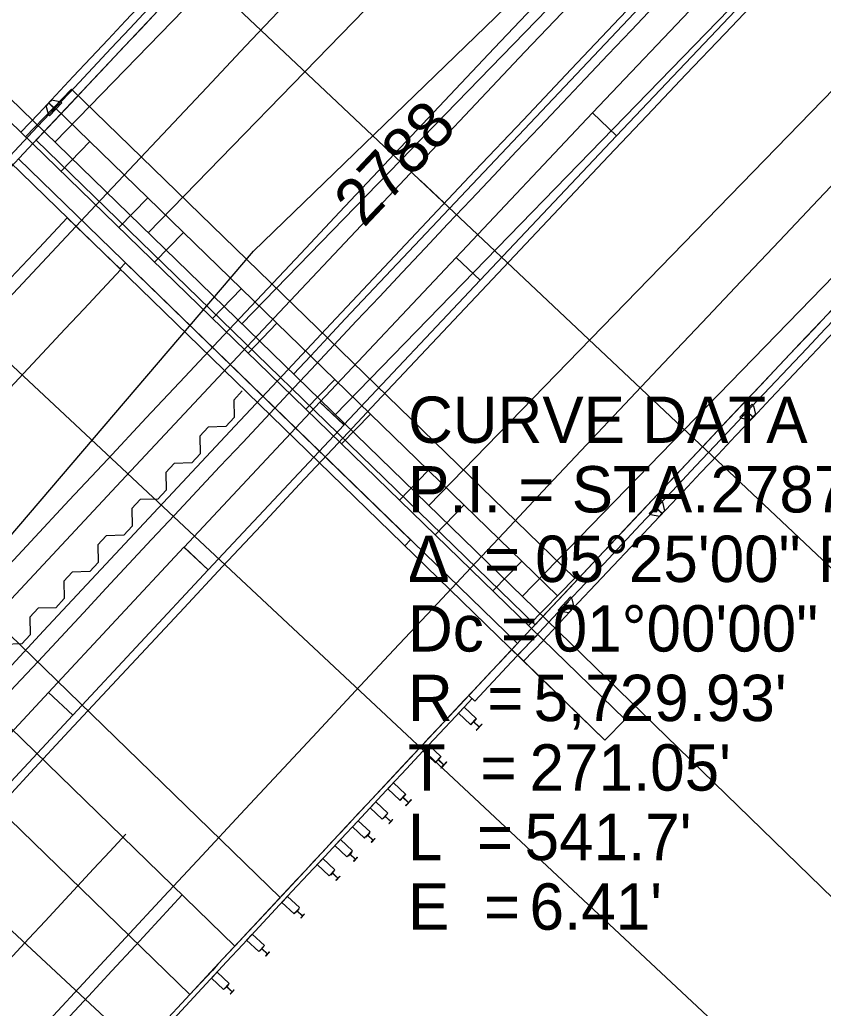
# Model space of a CAD drawing. Extents: x 2376379 to 2383101, y 559608 to 561720.
# Drawn here: x 2376981.5 to 2377030.1, y 561165 to 561224.7 of the extents above; entities that cross this region are included whole.
import ezdxf

# ---------------------------------------------------------------- set-up
doc = ezdxf.new("R2010")
doc.units = 0
for name, color, linetype in [('BR_X_SV_Bottom_of_Beam', 7, 'Continuous'), ('BR_X_SV_Deck_Top', 7, 'Continuous'), ('DR_X_Headwall', 7, 'Continuous'), ('DR_X_Storm_Sewer', 7, 'Continuous'), ('DT_X_Terrain_Ground_Line', 7, 'Continuous'), ('HY_X_Water_Edge', 7, 'Continuous'), ('PM_X_CL_Dashed', 7, 'Continuous'), ('PM_X_CL_Pass_Proh_Lt', 7, 'Continuous'), ('PM_X_Edge_Line', 7, 'Continuous'), ('PM_X_Surveyed_Line', 7, 'Continuous'), ('PV_X_COP', 7, 'Continuous'), ('PV_X_EOP', 7, 'Continuous'), ('PV_X_Shoulder', 7, 'Continuous'), ('RD_X_Cells', 7, 'Continuous'), ('RD_X_GR_Lt', 7, 'Continuous'), ('SC_Scratch1', 7, 'Continuous'), ('SV_X_Break_Lines', 7, 'Continuous'), ('SV_X_Control_Cells_Found', 7, 'Continuous'), ('SV_X_Text', 7, 'Continuous'), ('UT_X_Gas_Cells', 7, 'Continuous')]:
    doc.layers.add(name, color=color, linetype=linetype)

msp = doc.modelspace()

# ---------------------------------------------------------------- linework, layer by layer
at = {"layer": 'BR_X_SV_Bottom_of_Beam'}
for p, q in [((2377024.396, 561227.73), (2377016.136, 561219.025)), ((2377025.847, 561226.353), (2377017.587, 561217.648)), ((2377016.135, 561219.023), (2377007.893, 561210.301)), ((2377016.135, 561219.023), (2377007.893, 561210.301)), ((2377016.135, 561219.023), (2377017.588, 561217.65)), ((2377016.135, 561219.023), (2377017.588, 561217.65)), ((2377016.136, 561219.025), (2377017.587, 561217.648)), ((2377017.588, 561217.65), (2377009.347, 561208.927)), ((2377017.588, 561217.65), (2377009.347, 561208.927)), ((2377007.892, 561210.299), (2376999.669, 561201.56)), ((2377007.892, 561210.299), (2377009.348, 561208.929)), ((2377007.893, 561210.301), (2377009.347, 561208.927)), ((2377007.893, 561210.301), (2377009.347, 561208.927)), ((2377009.348, 561208.929), (2377001.125, 561200.189)), ((2376999.667, 561201.558), (2376991.462, 561192.802)), ((2376999.667, 561201.558), (2377001.127, 561200.191)), ((2376999.669, 561201.56), (2377001.125, 561200.189)), ((2377001.127, 561200.191), (2376992.922, 561191.434)), ((2376991.461, 561192.8), (2376983.275, 561184.026)), ((2376991.461, 561192.8), (2376992.923, 561191.436)), ((2376991.462, 561192.802), (2376992.922, 561191.434)), ((2376992.923, 561191.436), (2376984.737, 561182.662)), ((2376983.273, 561184.025), (2376975.105, 561175.234)), ((2376983.273, 561184.025), (2376984.738, 561182.663)), ((2376983.275, 561184.026), (2376984.737, 561182.662)), ((2376984.738, 561182.663), (2376976.57, 561173.872))]:
    msp.add_line(p, q, dxfattribs=at)
for radius in [5724.68, 5713.68]:
    msp.add_arc((2381174.86, 557281.309), radius, 134.056462, 138.414594, dxfattribs=at)
at = {"layer": 'BR_X_SV_Deck_Top'}
msp.add_line((2376984.409, 561212.699), (2376987.637, 561209.563), dxfattribs=at)
for radius, start, end in [(5745.93, 136.8269349, 138.4145938), (5741.43, 136.8277185, 138.9145631)]:
    msp.add_arc((2381174.86, 557281.309), radius, start, end, dxfattribs=at)
at = {"layer": 'DR_X_Headwall'}
msp.add_arc((2381174.86, 557281.309), 5712.93, 137.078423, 138.414594, dxfattribs=at)
at = {"layer": 'DR_X_Storm_Sewer'}
for p, q in [((2376981.472, 561216.25), (2377011.6, 561186.979)), ((2376964.404, 561197.983), (2376994.536, 561168.709))]:
    msp.add_line(p, q, dxfattribs=at)
msp.add_arc((2381174.917, 557281.256), 5708.58, 136.828468, 137.079388, dxfattribs=at)
at = {"layer": 'DT_X_Terrain_Ground_Line'}
for p, q in [((2376967.13, 561200.911), (2376997.261, 561171.638)), ((2376961.68, 561195.052), (2376991.812, 561165.778))]:
    msp.add_line(p, q, dxfattribs=at)
msp.add_arc((2381174.86, 557281.309), 5708.502, 137.039237, 137.119552, dxfattribs=at)
at = {"layer": 'HY_X_Water_Edge'}
msp.add_line((2376918.197, 561280.86), (2377079.942, 561123.72), dxfattribs=at)
at = {"layer": 'PM_X_CL_Dashed'}
for p, q in [((2377025.645, 561201.168), (2377025.302, 561200.805)), ((2377025.66, 561201.153), (2377025.496, 561200.979)), ((2377025.645, 561201.168), (2377025.845, 561201.38)), ((2377025.645, 561201.168), (2377025.66, 561201.153)), ((2377025.845, 561201.38), (2377025.785, 561201.438)), ((2377025.853, 561201.328), (2377025.823, 561201.357)), ((2377025.853, 561201.328), (2377025.976, 561200.823)), ((2377025.101, 561200.593), (2377025.041, 561200.65)), ((2377025.101, 561200.593), (2377025.302, 561200.805)), ((2377025.154, 561200.587), (2377025.123, 561200.616)), ((2377025.154, 561200.587), (2377025.665, 561200.494)), ((2377025.302, 561200.805), (2377025.318, 561200.79)), ((2377025.482, 561200.965), (2377025.318, 561200.79)), ((2377025.482, 561200.965), (2377025.814, 561200.652)), ((2377025.496, 561200.979), (2377025.827, 561200.666)), ((2377025.814, 561200.652), (2377025.649, 561200.477)), ((2377025.649, 561200.477), (2377025.665, 561200.462)), ((2377026.007, 561200.825), (2377025.665, 561200.462)), ((2377025.992, 561200.84), (2377025.827, 561200.666)), ((2377025.992, 561200.84), (2377026.007, 561200.825)), ((2377020.155, 561195.349), (2377019.813, 561194.986)), ((2377019.993, 561195.146), (2377019.829, 561194.971)), ((2377019.993, 561195.146), (2377020.325, 561194.833)), ((2377020.171, 561195.334), (2377020.007, 561195.16)), ((2377020.007, 561195.16), (2377020.338, 561194.847)), ((2377020.155, 561195.349), (2377020.356, 561195.562)), ((2377020.155, 561195.349), (2377020.171, 561195.334)), ((2377020.356, 561195.562), (2377020.295, 561195.619)), ((2377020.364, 561195.51), (2377020.334, 561195.539)), ((2377020.364, 561195.51), (2377020.487, 561195.005)), ((2377019.613, 561194.773), (2377019.552, 561194.831)), ((2377019.613, 561194.773), (2377019.813, 561194.986)), ((2377019.665, 561194.768), (2377019.635, 561194.797)), ((2377019.665, 561194.768), (2377020.177, 561194.676)), ((2377019.813, 561194.986), (2377019.829, 561194.971)), ((2377020.325, 561194.833), (2377020.161, 561194.659)), ((2377020.161, 561194.659), (2377020.176, 561194.644)), ((2377020.519, 561195.007), (2377020.176, 561194.644)), ((2377020.503, 561195.022), (2377020.338, 561194.847)), ((2377020.503, 561195.022), (2377020.519, 561195.007)), ((2377014.674, 561189.523), (2377014.874, 561189.736)), ((2377014.874, 561189.736), (2377014.813, 561189.793)), ((2377014.883, 561189.684), (2377014.852, 561189.713)), ((2377014.132, 561188.946), (2377014.332, 561189.159)), ((2377014.674, 561189.523), (2377014.332, 561189.159)), ((2377014.332, 561189.159), (2377014.348, 561189.144)), ((2377014.513, 561189.319), (2377014.348, 561189.144)), ((2377014.513, 561189.319), (2377014.845, 561189.007)), ((2377014.69, 561189.508), (2377014.526, 561189.333)), ((2377014.526, 561189.333), (2377014.858, 561189.021)), ((2377014.674, 561189.523), (2377014.69, 561189.508)), ((2377015.038, 561189.181), (2377014.696, 561188.817)), ((2377015.022, 561189.196), (2377014.858, 561189.021)), ((2377014.883, 561189.684), (2377015.006, 561189.179)), ((2377015.022, 561189.196), (2377015.038, 561189.181)), ((2377014.132, 561188.946), (2377014.072, 561189.003)), ((2377014.185, 561188.941), (2377014.154, 561188.97)), ((2377014.185, 561188.941), (2377014.697, 561188.849)), ((2377014.845, 561189.007), (2377014.68, 561188.832)), ((2377014.68, 561188.832), (2377014.696, 561188.817)), ((2377009.03, 561183.507), (2377008.666, 561183.849)), ((2377008.038, 561182.767), (2377008.38, 561183.132)), ((2377009.11, 561182.448), (2377008.38, 561183.132)), ((2377008.768, 561182.083), (2377008.038, 561182.767)), ((2377009.109, 561182.448), (2377008.768, 561182.084)), ((2377008.768, 561182.084), (2377008.784, 561182.069)), ((2377008.948, 561182.244), (2377008.784, 561182.069)), ((2377008.948, 561182.244), (2377009.281, 561181.932)), ((2377009.125, 561182.433), (2377008.961, 561182.258)), ((2377008.961, 561182.258), (2377009.294, 561181.946)), ((2377009.109, 561182.448), (2377009.125, 561182.433)), ((2377009.474, 561182.107), (2377009.132, 561181.742)), ((2377009.458, 561182.122), (2377009.294, 561181.946)), ((2377009.458, 561182.122), (2377009.474, 561182.107)), ((2377009.281, 561181.932), (2377009.117, 561181.757)), ((2377009.117, 561181.757), (2377009.132, 561181.742)), ((2377005.903, 561180.485), (2377006.244, 561180.85)), ((2377006.975, 561180.167), (2377006.244, 561180.85)), ((2377006.633, 561179.802), (2377005.903, 561180.485)), ((2377006.974, 561180.167), (2377006.633, 561179.802)), ((2377006.99, 561180.152), (2377006.826, 561179.977)), ((2377006.974, 561180.167), (2377006.99, 561180.152)), ((2377006.633, 561179.802), (2377006.649, 561179.788)), ((2377006.813, 561179.963), (2377006.649, 561179.788)), ((2377006.813, 561179.963), (2377007.146, 561179.652)), ((2377006.826, 561179.977), (2377007.159, 561179.666)), ((2377007.146, 561179.652), (2377006.982, 561179.476)), ((2377007.339, 561179.826), (2377006.998, 561179.461)), ((2377007.323, 561179.841), (2377007.159, 561179.666)), ((2377007.323, 561179.841), (2377007.339, 561179.826)), ((2377006.982, 561179.476), (2377006.998, 561179.461)), ((2377003.769, 561178.202), (2377004.11, 561178.568)), ((2377004.841, 561177.885), (2377004.11, 561178.568)), ((2377004.5, 561177.52), (2377003.769, 561178.202)), ((2377004.841, 561177.885), (2377004.5, 561177.52)), ((2377004.856, 561177.87), (2377004.693, 561177.695)), ((2377004.841, 561177.885), (2377004.856, 561177.87)), ((2377002.702, 561177.061), (2377003.044, 561177.426)), ((2377003.775, 561176.744), (2377003.044, 561177.426)), ((2377004.5, 561177.52), (2377004.516, 561177.505)), ((2377004.68, 561177.681), (2377004.516, 561177.505)), ((2377004.68, 561177.681), (2377005.013, 561177.369)), ((2377004.693, 561177.695), (2377005.026, 561177.383)), ((2377005.013, 561177.369), (2377004.849, 561177.194)), ((2377004.849, 561177.194), (2377004.865, 561177.179)), ((2377005.205, 561177.544), (2377004.865, 561177.179)), ((2377005.19, 561177.559), (2377005.026, 561177.383)), ((2377005.19, 561177.559), (2377005.205, 561177.544)), ((2377003.433, 561176.378), (2377002.702, 561177.061)), ((2377003.716, 561176.681), (2377003.492, 561176.441)), ((2377003.729, 561176.669), (2377003.622, 561176.554)), ((2377003.716, 561176.681), (2377003.775, 561176.744)), ((2377003.729, 561176.669), (2377003.716, 561176.681)), ((2377001.636, 561175.919), (2377001.977, 561176.284)), ((2377002.708, 561175.602), (2377001.977, 561176.284)), ((2377003.433, 561176.378), (2377003.492, 561176.441)), ((2377003.492, 561176.441), (2377003.505, 561176.429)), ((2377003.612, 561176.543), (2377003.505, 561176.429)), ((2377003.945, 561176.232), (2377003.612, 561176.543)), ((2377003.955, 561176.243), (2377003.622, 561176.554)), ((2377003.945, 561176.232), (2377003.838, 561176.118)), ((2377003.838, 561176.118), (2377003.851, 561176.105)), ((2377004.075, 561176.345), (2377003.851, 561176.105)), ((2377004.062, 561176.357), (2377003.955, 561176.243)), ((2377004.062, 561176.357), (2377004.075, 561176.345)), ((2377002.367, 561175.236), (2377001.636, 561175.919)), ((2377002.65, 561175.539), (2377002.426, 561175.299)), ((2377002.546, 561175.402), (2377002.439, 561175.287)), ((2377002.879, 561175.091), (2377002.546, 561175.402)), ((2377002.663, 561175.527), (2377002.556, 561175.412)), ((2377002.889, 561175.101), (2377002.556, 561175.412)), ((2377002.65, 561175.539), (2377002.708, 561175.602)), ((2377002.663, 561175.527), (2377002.65, 561175.539)), ((2377000.57, 561174.776), (2377000.911, 561175.142)), ((2377001.302, 561174.094), (2377000.57, 561174.776)), ((2377001.643, 561174.46), (2377000.911, 561175.142)), ((2377002.367, 561175.236), (2377002.426, 561175.299)), ((2377002.426, 561175.299), (2377002.439, 561175.287)), ((2377002.879, 561175.091), (2377002.772, 561174.976)), ((2377002.772, 561174.976), (2377002.785, 561174.963)), ((2377003.009, 561175.204), (2377002.785, 561174.963)), ((2377002.996, 561175.216), (2377002.889, 561175.101)), ((2377002.996, 561175.216), (2377003.009, 561175.204)), ((2377001.584, 561174.397), (2377001.36, 561174.157)), ((2377001.48, 561174.259), (2377001.373, 561174.145)), ((2377001.814, 561173.948), (2377001.48, 561174.259)), ((2377001.597, 561174.385), (2377001.49, 561174.27)), ((2377001.823, 561173.959), (2377001.49, 561174.27)), ((2377001.584, 561174.397), (2377001.643, 561174.46)), ((2377001.597, 561174.385), (2377001.584, 561174.397)), ((2376999.505, 561173.633), (2376999.846, 561173.999)), ((2377000.236, 561172.951), (2376999.505, 561173.633)), ((2377000.577, 561173.317), (2376999.846, 561173.999)), ((2377001.302, 561174.094), (2377001.36, 561174.157)), ((2377001.36, 561174.157), (2377001.373, 561174.145)), ((2377001.814, 561173.948), (2377001.707, 561173.834)), ((2377001.707, 561173.834), (2377001.72, 561173.821)), ((2377001.944, 561174.061), (2377001.72, 561173.821)), ((2377001.931, 561174.074), (2377001.823, 561173.959)), ((2377001.931, 561174.074), (2377001.944, 561174.061)), ((2377000.236, 561172.951), (2377000.295, 561173.014)), ((2377000.519, 561173.254), (2377000.295, 561173.014)), ((2377000.295, 561173.014), (2377000.308, 561173.002)), ((2377000.415, 561173.117), (2377000.308, 561173.002)), ((2377000.748, 561172.806), (2377000.415, 561173.117)), ((2377000.532, 561173.242), (2377000.425, 561173.127)), ((2377000.758, 561172.816), (2377000.425, 561173.127)), ((2377000.519, 561173.254), (2377000.577, 561173.317)), ((2377000.532, 561173.242), (2377000.519, 561173.254)), ((2377000.748, 561172.806), (2377000.641, 561172.691)), ((2377000.641, 561172.691), (2377000.654, 561172.679)), ((2377000.878, 561172.919), (2377000.654, 561172.679)), ((2377000.865, 561172.931), (2377000.758, 561172.816)), ((2377000.865, 561172.931), (2377000.878, 561172.919)), ((2376997.375, 561171.347), (2376997.715, 561171.713)), ((2376998.106, 561170.666), (2376997.375, 561171.347)), ((2376998.447, 561171.031), (2376997.715, 561171.713)), ((2376998.106, 561170.666), (2376998.165, 561170.728)), ((2376998.389, 561170.969), (2376998.165, 561170.728)), ((2376998.165, 561170.728), (2376998.178, 561170.716)), ((2376998.285, 561170.831), (2376998.178, 561170.716)), ((2376998.619, 561170.52), (2376998.285, 561170.831)), ((2376998.402, 561170.956), (2376998.295, 561170.842)), ((2376998.628, 561170.531), (2376998.295, 561170.842)), ((2376998.389, 561170.969), (2376998.447, 561171.031)), ((2376998.402, 561170.956), (2376998.389, 561170.969)), ((2376998.749, 561170.634), (2376998.525, 561170.393)), ((2376998.735, 561170.646), (2376998.628, 561170.531)), ((2376998.735, 561170.646), (2376998.749, 561170.634)), ((2376998.619, 561170.52), (2376998.512, 561170.406)), ((2376998.512, 561170.406), (2376998.525, 561170.393)), ((2376995.246, 561169.06), (2376995.586, 561169.426)), ((2376996.319, 561168.745), (2376995.586, 561169.426)), ((2376995.978, 561168.379), (2376995.246, 561169.06)), ((2376995.978, 561168.379), (2376996.036, 561168.441)), ((2376996.26, 561168.682), (2376996.036, 561168.441)), ((2376996.036, 561168.441), (2376996.05, 561168.429)), ((2376996.157, 561168.544), (2376996.05, 561168.429)), ((2376996.49, 561168.234), (2376996.157, 561168.544)), ((2376996.273, 561168.67), (2376996.166, 561168.555)), ((2376996.5, 561168.244), (2376996.166, 561168.555)), ((2376996.26, 561168.682), (2376996.319, 561168.745)), ((2376996.273, 561168.67), (2376996.26, 561168.682)), ((2376996.49, 561168.234), (2376996.383, 561168.119)), ((2376996.62, 561168.347), (2376996.396, 561168.106)), ((2376996.607, 561168.359), (2376996.5, 561168.244)), ((2376996.607, 561168.359), (2376996.62, 561168.347)), ((2376996.383, 561168.119), (2376996.396, 561168.106)), ((2376993.118, 561166.771), (2376993.458, 561167.137)), ((2376994.191, 561166.457), (2376993.458, 561167.137)), ((2376993.851, 561166.09), (2376993.118, 561166.771)), ((2376994.133, 561166.394), (2376994.191, 561166.457)), ((2376993.851, 561166.09), (2376993.909, 561166.153)), ((2376994.133, 561166.394), (2376993.909, 561166.153)), ((2376993.909, 561166.153), (2376993.922, 561166.141)), ((2376994.029, 561166.256), (2376993.922, 561166.141)), ((2376994.363, 561165.946), (2376994.029, 561166.256)), ((2376994.146, 561166.382), (2376994.039, 561166.266)), ((2376994.373, 561165.956), (2376994.039, 561166.266)), ((2376994.146, 561166.382), (2376994.133, 561166.394)), ((2376994.363, 561165.946), (2376994.256, 561165.831)), ((2376994.256, 561165.831), (2376994.269, 561165.819)), ((2376994.493, 561166.059), (2376994.269, 561165.819)), ((2376994.48, 561166.071), (2376994.373, 561165.956)), ((2376994.48, 561166.071), (2376994.493, 561166.059))]:
    msp.add_line(p, q, dxfattribs=at)
for points in [[(2377025.041, 561200.65), (2377025.041, 561200.65), (2377025.785, 561201.438)], [(2377019.552, 561194.831), (2377019.552, 561194.831), (2377020.295, 561195.619)], [(2377014.072, 561189.003), (2377014.072, 561189.003), (2377014.813, 561189.793)]]:
    msp.add_lwpolyline(points, dxfattribs=at)
for centre, radius, start, end in [((2381174.86, 557281.309), 5708.502, 134.056462, 138.734789), ((2381174.86, 557281.309), 5708.002, 134.783851, 136.871541), ((2381174.917, 557281.256), 5708.299, 136.871538, 138.73476)]:
    msp.add_arc(centre, radius, start, end, dxfattribs=at)
at = {"layer": 'PM_X_CL_Pass_Proh_Lt'}
for p, q in [((2376983.111, 561219.456), (2376983.453, 561219.82)), ((2376983.127, 561219.441), (2376983.291, 561219.616)), ((2376983.624, 561219.304), (2376983.291, 561219.616)), ((2376983.305, 561219.63), (2376983.469, 561219.805)), ((2376983.637, 561219.318), (2376983.305, 561219.63)), ((2376983.469, 561219.805), (2376983.453, 561219.82)), ((2376983.965, 561219.696), (2376983.453, 561219.788)), ((2376984.017, 561219.691), (2376983.817, 561219.478)), ((2376983.965, 561219.696), (2376983.995, 561219.668)), ((2376984.017, 561219.691), (2376984.078, 561219.634)), ((2376983.127, 561219.441), (2376983.111, 561219.456)), ((2376983.267, 561218.954), (2376983.143, 561219.459)), ((2376983.267, 561218.954), (2376983.297, 561218.925)), ((2376983.475, 561219.115), (2376983.275, 561218.902)), ((2376983.459, 561219.129), (2376983.624, 561219.304)), ((2376983.475, 561219.115), (2376983.459, 561219.129)), ((2376983.475, 561219.115), (2376983.817, 561219.478)), ((2376983.637, 561219.318), (2376983.801, 561219.493)), ((2376983.817, 561219.478), (2376983.801, 561219.493)), ((2376983.275, 561218.902), (2376983.336, 561218.845))]:
    msp.add_line(p, q, dxfattribs=at)
msp.add_lwpolyline([(2376984.078, 561219.634), (2376984.078, 561219.634), (2376983.336, 561218.845)], dxfattribs=at)
for centre, radius, start, end in [((2381174.86, 557281.309), 5750.502, 134.4393655, 138.0925584), ((2381174.917, 557281.256), 5751.08, 134.7915077, 136.8639244)]:
    msp.add_arc(centre, radius, start, end, dxfattribs=at)
at = {"layer": 'PM_X_Edge_Line'}
msp.add_line((2376982.541, 561217.39), (2377012.67, 561188.119), dxfattribs=at)
for centre, radius, start, end in [((2381174.86, 557281.309), 5728.92, 134.539622, 137.114945), ((2381174.917, 557281.256), 5750.58, 134.8496279, 136.8055852), ((2381174.917, 557281.256), 5708.58, 134.842434, 136.812784)]:
    msp.add_arc(centre, radius, start, end, dxfattribs=at)
at = {"layer": 'PM_X_Surveyed_Line'}
for p, q in [((2377094.477, 561131.217), (2376919.913, 561295.921)), ((2376902.438, 561277.318), (2377077.719, 561113.377)), ((2377061.038, 561095.465), (2376885.044, 561258.639))]:
    msp.add_line(p, q, dxfattribs=at)
at = {"layer": 'PV_X_COP'}
for p, q in [((2377012.053, 561222.712), (2377020.313, 561231.418)), ((2377003.811, 561213.989), (2377012.052, 561222.711)), ((2376995.587, 561205.248), (2377003.81, 561213.988)), ((2376987.381, 561196.49), (2376995.586, 561205.247)), ((2376979.194, 561187.715), (2376987.38, 561196.489))]:
    msp.add_line(p, q, dxfattribs=at)
for radius in [5745.18, 5734.18]:
    msp.add_arc((2381174.86, 557281.309), radius, 134.0564619, 138.4145938, dxfattribs=at)
at = {"layer": 'PV_X_EOP'}
msp.add_line((2377007.195, 561213.569), (2377005.74, 561214.941), dxfattribs=at)
at = {"layer": 'PV_X_Shoulder'}
msp.add_arc((2381174.917, 557281.256), 5729.58, 134.8522952, 136.8022952, dxfattribs=at)
at = {"layer": 'RD_X_Cells'}
for p, q in [((2376995.664, 561210.671), (2377447.664, 561648.024)), ((2376415.939, 560532.545), (2376995.664, 561210.671))]:
    msp.add_line(p, q, dxfattribs=at)
msp.add_arc((2381174.86, 557281.309), 5729.93, 134.0564619, 139.4731285, dxfattribs=at)
msp.add_arc((2381174.86, 557281.309), 5729.93, 134.0564619, 139.4731285, dxfattribs=at)
at = {"layer": 'SC_Scratch1'}
for p, q in [((2376975.07, 561224.212), (2377018.105, 561182.403)), ((2377016.885, 561181.148), (2377011.258, 561186.615)), ((2377018.105, 561182.403), (2377016.885, 561181.148))]:
    msp.add_line(p, q, dxfattribs=at)
at = {"layer": 'SV_X_Break_Lines'}
for p, q in [((2376994.977, 561202.235), (2376994.463, 561201.688)), ((2376994.463, 561201.688), (2376994.497, 561200.628)), ((2376994.497, 561200.628), (2376993.983, 561200.081)), ((2376992.923, 561200.048), (2376992.41, 561199.501)), ((2376993.983, 561200.081), (2376992.923, 561200.048)), ((2376992.41, 561199.501), (2376992.443, 561198.441)), ((2376992.443, 561198.441), (2376991.93, 561197.894)), ((2376990.87, 561197.861), (2376990.356, 561197.314)), ((2376991.93, 561197.894), (2376990.87, 561197.861)), ((2376990.356, 561197.314), (2376990.39, 561196.254)), ((2376988.816, 561195.674), (2376988.303, 561195.127)), ((2376989.876, 561195.707), (2376988.816, 561195.674)), ((2376990.39, 561196.254), (2376989.876, 561195.707)), ((2376988.303, 561195.127), (2376988.336, 561194.067)), ((2376988.336, 561194.067), (2376987.823, 561193.52)), ((2376986.763, 561193.487), (2376986.249, 561192.94)), ((2376987.823, 561193.52), (2376986.763, 561193.487)), ((2376986.249, 561192.94), (2376986.283, 561191.88)), ((2376986.283, 561191.88), (2376985.769, 561191.333)), ((2376984.709, 561191.3), (2376984.196, 561190.753)), ((2376985.769, 561191.333), (2376984.709, 561191.3)), ((2376984.196, 561190.753), (2376984.229, 561189.693)), ((2376982.655, 561189.113), (2376982.142, 561188.566)), ((2376983.716, 561189.146), (2376982.655, 561189.113)), ((2376984.229, 561189.693), (2376983.716, 561189.146)), ((2376982.142, 561188.566), (2376982.175, 561187.506)), ((2376982.175, 561187.506), (2376981.662, 561186.959)), ((2376981.662, 561186.959), (2376980.602, 561186.926))]:
    msp.add_line(p, q, dxfattribs=at)
at = {"layer": 'SV_X_Control_Cells_Found'}
for p, q in [((2376975.07, 561224.212), (2377018.105, 561182.403)), ((2376973.851, 561222.957), (2377016.885, 561181.148)), ((2376981.884, 561217.593), (2376984.671, 561220.462)), ((2376984.671, 561220.462), (2377015.064, 561190.934)), ((2376983.626, 561219.386), (2377014.019, 561189.858)), ((2376985.778, 561217.295), (2376984.036, 561215.502)), ((2376989.274, 561213.898), (2376987.532, 561212.105)), ((2376991.426, 561211.808), (2376989.684, 561210.015)), ((2376987.583, 561209.616), (2376987.931, 561209.975)), ((2376987.931, 561209.975), (2377005.145, 561193.251)), ((2376994.922, 561208.411), (2376993.18, 561206.618)), ((2376997.074, 561206.32), (2376995.332, 561204.527)), ((2377000.571, 561202.923), (2376998.829, 561201.13)), ((2377002.722, 561200.833), (2377000.98, 561199.04)), ((2377006.219, 561197.436), (2377004.477, 561195.643)), ((2377008.371, 561195.345), (2377006.629, 561193.552)), ((2377004.797, 561192.892), (2377005.145, 561193.251)), ((2377011.867, 561191.948), (2377010.125, 561190.155)), ((2377015.064, 561190.934), (2377012.277, 561188.065)), ((2377011.61, 561186.272), (2377012.83, 561187.528)), ((2377011.969, 561185.924), (2377013.189, 561187.179)), ((2377016.885, 561181.148), (2377018.105, 561182.403))]:
    msp.add_line(p, q, dxfattribs=at)
for radius, start, end in [(5751.58, 134.8460617, 136.8085286), (5707.58, 134.838497, 136.816094)]:
    msp.add_arc((2381174.917, 557281.256), radius, start, end, dxfattribs=at)
at = {"layer": 'SV_X_Text'}
msp.add_arc((2381174.86, 557281.309), 5717.93, 137.074711, 138.914563, dxfattribs=at)
at = {"layer": 'UT_X_Gas_Cells'}
for p, q in [((2377119.531, 561357.12), (2376983.657, 561217.265)), ((2377125.179, 561351.633), (2376989.305, 561211.777)), ((2377130.827, 561346.145), (2376994.953, 561206.29)), ((2377136.475, 561340.658), (2377000.601, 561200.802)), ((2377142.124, 561335.17), (2377006.25, 561195.315)), ((2377147.772, 561329.683), (2377011.898, 561189.827))]:
    msp.add_line(p, q, dxfattribs=at)

# ---------------------------------------------------------------- texts
at = {"layer": 'PV_X_EOP'}
msp.add_text('2788', height=2.8, rotation=46.6647, dxfattribs=at).set_placement((2377002.321, 561212.046))
at = {"layer": 'RD_X_GR_Lt'}
for s, p in [('CURVE DATA', (2377004.995, 561199.098)), ('P.I. = STA. ', (2377004.995, 561194.898)), ('2787+90.19', (2377023.262, 561194.898)), ('Δ  = ', (2377004.995, 561190.698)), ('05°25\'00" RT', (2377012.672, 561190.698)), ('Dc = ', (2377004.995, 561186.498)), ('01°00\'00"', (2377013.734, 561186.498)), ('R  = ', (2377004.995, 561182.298)), ("5,729.93'", (2377012.577, 561182.298)), ('T  = ', (2377004.995, 561178.098)), ("271.05'", (2377012.333, 561178.098)), ('L  = ', (2377004.995, 561173.898)), ("541.7'", (2377012.036, 561173.898)), ('E  = ', (2377004.995, 561169.698)), ("6.41'", (2377012.335, 561169.698))]:
    msp.add_text(s, height=2.8, dxfattribs=at).set_placement(p)

doc.saveas('drawing.dxf')
